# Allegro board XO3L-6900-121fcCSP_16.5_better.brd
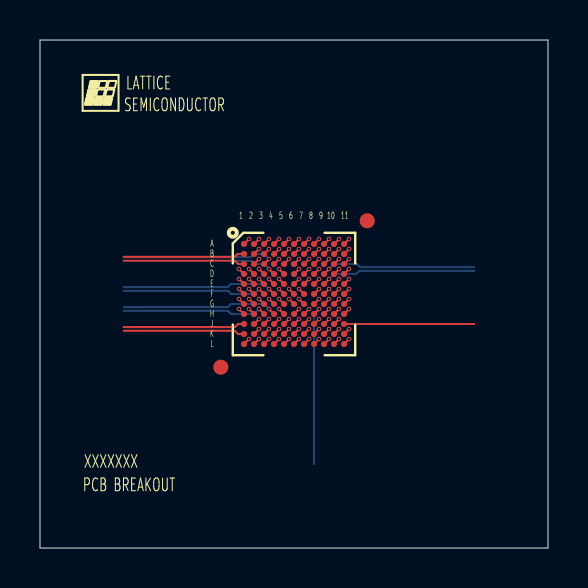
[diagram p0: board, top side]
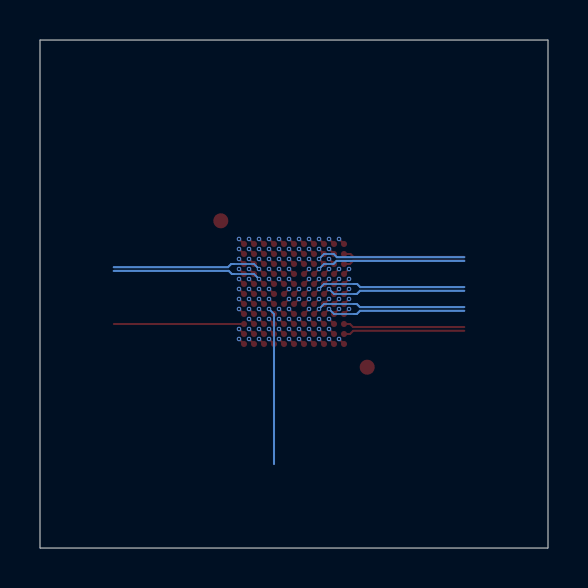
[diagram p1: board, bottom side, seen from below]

Outline 25.4 x 25.4 mm; copper layers: TOP, L2_GND, L3_SIGNAL1, L4_SIGNAL2, L5_PWR, BOTTOM. Coordinates in mm from the lower left corner of the outline.
Outline path: 0,25.4 25.4,25.4 25.4,0 0,0 0,25.4

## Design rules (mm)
net group CDPL10: nets PL10C PL10D
net group CDPT13: nets PT13C PT13D
net group CDPT15: nets PT15C PT15D
net group CDPT20: nets PT20C PT20D
net group CDPT23: nets PT23C PT23D
net group CDPT28: nets PT28C PT28D
net group PB3: nets PB3A PB3B
net group PB4: nets PB4A PB4B
net group PB7: nets PB7A PB7B
net group PB9: nets PB9A PB9B
net group PB10: nets PB10A PB10B
net group PB13: nets PB13A PB13B
net group PB20: nets PB20A PB20B
net group PB21: nets PB21A PB21B
net group PB24: nets PB24A PB24B
net group PB27: nets PB27A PB27B
net group PB29: nets PB29A PB29B
net group PB30: nets PB30A PB30B
net group PL3: nets PL3A PL3B
net group PL4: nets PL4A PL4B
net group PL6: nets PL6A PL6B
net group PL7: nets PL7A PL7B
net group PL8: nets PL8A PL8B
net group PL9: nets PL9A PL9B
net group PL14: nets PL14A PL14B
net group PL16: nets PL16A PL16B
net group PL17: nets PL17A PL17B
net group PL20: nets PL20A PL20B
net group PR2: nets PR2A PR2B
net group PR3: nets PR3A PR3B
net group PR5: nets PR5A PR5B
net group PR6: nets PR6A PR6B
net group PR8: nets PR8A PR8B
net group PR9: nets PR9A PR9B
net group PR10: nets PR10A PR10B
net group PR13: nets PR13A PR13B
net group PR14: nets PR14A PR14B
net group PR15: nets PR15A PR15B
net group PR16: nets PR16A PR16B
net group PR18: nets PR18A PR18B
net group PR19: nets PR19A PR19B
net group PT9: nets PT9A PT9B
net group PT11: nets PT11A PT11B
net group PT14: nets PT14A PT14B
net group PT18: nets PT18A PT18B
net group PT21: nets PT21A PT21B
net group PT24: nets PT24A PT24B
net group PT27: nets PT27A PT27B

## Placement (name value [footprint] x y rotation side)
BGA  -  [BGA121N50P11X11_600X600X100B-1]  12.7 12.7 270 top
NOREF  -  []  1.85 21.54 0 top

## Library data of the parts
BGA = BGA121N50P11X11_600X600X100B-1

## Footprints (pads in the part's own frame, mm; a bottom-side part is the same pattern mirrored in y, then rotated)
BGA121N50P11X11_600X600X100B-1
  round 0.75 smd: (-3.66,3.66) (3.66,-3.66)
  round 0.305 smd: A1(-2.5,-2.5) A2(-2.5,-2) A3(-2.5,-1.5) A4(-2.5,-1) A5(-2.5,-0.5) A6(-2.5,0) A7(-2.5,0.5) A8(-2.5,1) A9(-2.5,1.5) A10(-2.5,2) A11(-2.5,2.5) B1(-2,-2.5) B2(-2,-2) B3(-2,-1.5) B4(-2,-1) B5(-2,-0.5) B6(-2,0) B7(-2,0.5) B8(-2,1) B9(-2,1.5) B10(-2,2) B11(-2,2.5) C1(-1.5,-2.5) C2(-1.5,-2) C3(-1.5,-1.5) C4(-1.5,-1) C5(-1.5,-0.5) C6(-1.5,0) C7(-1.5,0.5) C8(-1.5,1) C9(-1.5,1.5) C10(-1.5,2) C11(-1.5,2.5) D1(-1,-2.5) D2(-1,-2) D3(-1,-1.5) D4(-1,-1) D5(-1,-0.5) D6(-1,0) D7(-1,0.5) D8(-1,1) D9(-1,1.5) D10(-1,2) D11(-1,2.5) E1(-0.5,-2.5) E2(-0.5,-2) E3(-0.5,-1.5) E4(-0.5,-1) E5(-0.5,-0.5) E6(-0.5,0) E7(-0.5,0.5) E8(-0.5,1) E9(-0.5,1.5) E10(-0.5,2) E11(-0.5,2.5) F1(0,-2.5) F2(0,-2) F3(0,-1.5) F4(0,-1) F5(0,-0.5) F6(0,0) F7(0,0.5) F8(0,1) F9(0,1.5) F10(0,2) F11(0,2.5) G1(0.5,-2.5) G2(0.5,-2) G3(0.5,-1.5) G4(0.5,-1) G5(0.5,-0.5) G6(0.5,0) G7(0.5,0.5) G8(0.5,1) G9(0.5,1.5) G10(0.5,2) G11(0.5,2.5) H1(1,-2.5) H2(1,-2) H3(1,-1.5) H4(1,-1) H5(1,-0.5) H6(1,0) H7(1,0.5) H8(1,1) H9(1,1.5) H10(1,2) H11(1,2.5) J1(1.5,-2.5) J2(1.5,-2) J3(1.5,-1.5) J4(1.5,-1) J5(1.5,-0.5) J6(1.5,0) J7(1.5,0.5) J8(1.5,1) J9(1.5,1.5) J10(1.5,2) J11(1.5,2.5) K1(2,-2.5) K2(2,-2) K3(2,-1.5) K4(2,-1) K5(2,-0.5) K6(2,0) K7(2,0.5) K8(2,1) K9(2,1.5) K10(2,2) K11(2,2.5) L1(2.5,-2.5) L2(2.5,-2) L3(2.5,-1.5) L4(2.5,-1) L5(2.5,-0.5) L6(2.5,0) L7(2.5,0.5) L8(2.5,1) L9(2.5,1.5) L10(2.5,2) L11(2.5,2.5)

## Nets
GND: BGA.A1 BGA.A11 BGA.E6 BGA.E7 BGA.F5 BGA.F6 BGA.G5 BGA.G6 BGA.L1 BGA.L11
VCC: BGA.D5 BGA.E5 BGA.F7 BGA.G7
VCCIO0: BGA.D6
VCCIO1: BGA.H5
VCCIO2: BGA.H6
VCCIO3: BGA.H8
VCCIO4: BGA.F8
VCCIO5: BGA.D8
PB3A: BGA.H9
PB3B: BGA.J9
PB4A: BGA.K10
PB4B: BGA.L10
PB7A: BGA.K9
PB7B: BGA.L9
PB9A: BGA.J8
PB9B: BGA.H7
PB10A: BGA.K8
PB10B: BGA.L8
PB13A: BGA.L7
PB13B: BGA.K7
PB15B: BGA.J7
PB20A: BGA.L6
PB20B: BGA.K6
PB21A: BGA.L5
PB21B: BGA.K5
PB23A: BGA.J6
PB24A: BGA.L4
PB24B: BGA.K4
PB27A: BGA.J5
PB27B: BGA.J4
PB29A: BGA.L3
PB29B: BGA.K3
PB30A: BGA.L2
PB30B: BGA.K2
PL3A: BGA.C9
PL3B: BGA.E8
PL4A: BGA.B10
PL4B: BGA.B11
PL6A: BGA.C10
PL6B: BGA.C11
PL7A: BGA.D9
PL7B: BGA.E9
PL8A: BGA.D10
PL8B: BGA.D11
PL9A: BGA.E10
PL9B: BGA.E11
PL10C: BGA.F11
PL10D: BGA.F10
PL13A: BGA.F9
PL14A: BGA.G11
PL14B: BGA.G10
PL16A: BGA.G9
PL16B: BGA.G8
PL17A: BGA.H11
PL17B: BGA.H10
PL19A: BGA.J11
PL20A: BGA.K11
PL20B: BGA.J10
PR2A: BGA.C2
PR2B: BGA.D3
PR3A: BGA.B1
PR3B: BGA.C1
PR5A: BGA.D2
PR5B: BGA.D1
PR6A: BGA.E4
PR6B: BGA.E3
PR8A: BGA.E2
PR8B: BGA.E1
PR9A: BGA.F3
PR9B: BGA.F4
PR10A: BGA.F2
PR10B: BGA.F1
PR13A: BGA.G1
PR13B: BGA.G2
PR14A: BGA.G3
PR14B: BGA.G4
PR15A: BGA.H1
PR15B: BGA.H2
PR16A: BGA.H3
PR16B: BGA.H4
PR18A: BGA.J1
PR18B: BGA.K1
PR19A: BGA.J2
PR19B: BGA.J3
PT9A: BGA.A10
PT9B: BGA.B9
PT10A: BGA.C8
PT11A: BGA.A9
PT11B: BGA.B8
PT13C: BGA.D7
PT13D: BGA.A8
PT14A: BGA.A7
PT14B: BGA.B7
PT15C: BGA.C7
PT15D: BGA.C6
PT18A: BGA.B6
PT18B: BGA.A6
PT20C: BGA.A5
PT20D: BGA.B5
PT21A: BGA.A4
PT21B: BGA.B4
PT23C: BGA.C5
PT23D: BGA.C4
PT24A: BGA.A3
PT24B: BGA.B3
PT27A: BGA.A2
PT27B: BGA.B2
PT28C: BGA.C3
PT28D: BGA.D4

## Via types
v1: diameter 0.224, hole 0.127, TOP to BOTTOM, 116 vias

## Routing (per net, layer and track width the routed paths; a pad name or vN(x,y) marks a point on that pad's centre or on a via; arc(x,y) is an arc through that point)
GND: length 3.5
  TOP w0.102: BGA.E7 v1(13.45,13.45) ; BGA.A1 v1(10.45,15.45) ; BGA.E6 v1(12.95,13.45) ; BGA.L11 v1(15.45,10.45) ; BGA.A11 v1(15.45,15.45) ; BGA.F6 v1(12.45,12.95) ; BGA.F5 v1(11.95,12.95) ; BGA.G5 v1(11.95,12.45) ; BGA.L1 v1(10.45,10.45) ; BGA.G6 v1(12.45,12.45)
VCC: length 1.4
  TOP w0.102: BGA.D5 v1(11.95,13.95) ; BGA.G7 v1(12.95,12.45) ; BGA.E5 v1(11.95,13.45) ; BGA.F7 v1(12.95,12.95)
VCCIO0: length 0.4
  TOP w0.102: BGA.D6 v1(12.95,13.95)
VCCIO1: length 0.4
  TOP w0.102: BGA.H5 v1(11.95,11.95)
VCCIO2: length 0.4
  TOP w0.102: BGA.H6 v1(12.95,11.95)
VCCIO3: length 8.2
  TOP w0.102: BGA.H8 v1(13.95,11.95)
  BOTTOM w0.089: v1(13.95,11.95) BGA.H8 13.7,10.22
  BOTTOM w0.102: 13.7,4.2 13.7,10.22
VCCIO4: length 0.4
  TOP w0.102: BGA.F8 v1(13.95,12.95)
VCCIO5: length 0.4
  TOP w0.102: BGA.D8 v1(13.95,13.95)
PB3A: length 7.8
  TOP w0.102: BGA.H9 v1(14.45,11.95)
  L4_SIGNAL2 w0.089: 15.21,11.7 14.7,11.7 v1(14.45,11.95)
  L4_SIGNAL2 w0.102: 15.21,11.7 15.37,11.54 21.71,11.54
PB3B: length 7.8
  TOP w0.102: BGA.J9 v1(14.45,11.45)
  L4_SIGNAL2 w0.089: 15.21,11.2 14.7,11.2 v1(14.45,11.45)
  L4_SIGNAL2 w0.102: 15.21,11.2 15.36,11.35 21.71,11.35
PB4A: length 7.2
  TOP w0.102: BGA.K10 v1(14.95,10.95)
  L3_SIGNAL1 w0.089: 14.7,10.22 BGA.K10 v1(14.95,10.95)
  L3_SIGNAL1 w0.102: 14.7,4.19 14.7,10.22
PB4B: length 6.6
  TOP w0.102: BGA.L10 v1(14.95,10.45)
  L3_SIGNAL1 w0.102: v1(14.95,10.45) 14.95,10.16 14.89,10.09 14.89,4.19
PB7A: length 7.2
  TOP w0.102: BGA.K9 v1(14.45,10.95)
  L3_SIGNAL1 w0.089: v1(14.45,10.95) BGA.K9 14.2,10.22
  L3_SIGNAL1 w0.102: 14.2,4.19 14.2,10.22
PB7B: length 6.6
  TOP w0.102: BGA.L9 v1(14.45,10.45)
  L3_SIGNAL1 w0.102: 14.39,4.19 14.39,10.09 14.45,10.16 v1(14.45,10.45)
PB9A: length 7.8
  TOP w0.102: BGA.J8 v1(13.95,11.45)
  L4_SIGNAL2 w0.089: 14.2,10.21 14.2,11.2 v1(13.95,11.45)
  L4_SIGNAL2 w0.102: 14.2,10.21 14.2,10.06 14.06,9.92 14.06,4.19
PB9B: length 8.3
  TOP w0.102: BGA.H7 v1(13.45,11.95)
  L4_SIGNAL2 w0.089: 13.7,10.26 13.7,11.7 v1(13.45,11.95)
  L4_SIGNAL2 w0.102: 13.7,10.26 13.7,10.08 13.87,9.91 13.87,4.19
PB10A: length 7.2
  TOP w0.102: BGA.K8 v1(13.95,10.95)
  L3_SIGNAL1 w0.089: v1(13.95,10.95) BGA.K8 13.7,10.22
  L3_SIGNAL1 w0.102: 13.7,4.19 13.7,10.22
PB10B: length 6.6
  TOP w0.102: BGA.L8 v1(13.95,10.45)
  L3_SIGNAL1 w0.102: v1(13.95,10.45) 13.95,10.16 13.89,10.09 13.89,4.19
PB13A: length 6.6
  TOP w0.102: BGA.L7 v1(13.45,10.45)
  L3_SIGNAL1 w0.102: 13.39,4.19 13.39,10.09 13.45,10.16 v1(13.45,10.45)
PB13B: length 7.2
  TOP w0.102: BGA.K7 v1(13.45,10.95)
  L3_SIGNAL1 w0.089: 13.2,10.22 BGA.K7 v1(13.45,10.95)
  L3_SIGNAL1 w0.102: 13.2,4.19 13.2,10.22
PB15B: length 7.7
  TOP w0.102: BGA.J7 v1(13.45,11.45)
  L4_SIGNAL2 w0.089: 13.2,10.23 BGA.J7 v1(13.45,11.45)
  L4_SIGNAL2 w0.102: 13.2,4.19 13.2,10.23
PB20A: length 6.6
  TOP w0.102: BGA.L6 v1(12.95,10.45)
  L3_SIGNAL1 w0.102: 12.89,4.19 12.89,10.09 12.95,10.16 v1(12.95,10.45)
PB20B: length 7.2
  TOP w0.102: BGA.K6 v1(12.95,10.95)
  L3_SIGNAL1 w0.089: v1(12.95,10.95) BGA.K6 12.7,10.22
  L3_SIGNAL1 w0.102: 12.7,4.19 12.7,10.22
PB21A: length 6.6
  TOP w0.102: BGA.L5 v1(12.45,10.45)
  L3_SIGNAL1 w0.102: 12.39,4.19 12.39,10.09 12.45,10.16 v1(12.45,10.45)
PB21B: length 7.2
  TOP w0.102: BGA.K5 v1(12.45,10.95)
  L3_SIGNAL1 w0.089: 12.2,10.22 BGA.K5 v1(12.45,10.95)
  L3_SIGNAL1 w0.102: 12.2,4.19 12.2,10.22
PB23A: length 7.7
  TOP w0.102: BGA.J6 v1(12.95,11.45)
  L4_SIGNAL2 w0.089: 12.7,10.23 BGA.J6 v1(12.95,11.45)
  L4_SIGNAL2 w0.102: 12.7,4.19 12.7,10.23
PB24A: length 6.6
  TOP w0.102: BGA.L4 v1(11.95,10.45)
  L3_SIGNAL1 w0.102: 11.89,4.19 11.89,10.09 11.95,10.16 v1(11.95,10.45)
PB24B: length 7.2
  TOP w0.102: BGA.K4 v1(11.95,10.95)
  L3_SIGNAL1 w0.089: 11.7,10.22 BGA.K4 v1(11.95,10.95)
  L3_SIGNAL1 w0.102: 11.7,4.19 11.7,10.22
PB27A: length 7.8
  TOP w0.102: BGA.J5 v1(12.45,11.45)
  L4_SIGNAL2 w0.089: 12.2,10.23 12.2,11.05 12.45,11.3 v1(12.45,11.45)
  L4_SIGNAL2 w0.102: 12.2,10.23 12.2,10.08 12.03,9.91 12.03,4.19
PB27B: length 7.8
  TOP w0.102: BGA.J4 v1(11.95,11.45)
  L4_SIGNAL2 w0.089: v1(11.95,11.45) BGA.J4 11.7,10.21
  L4_SIGNAL2 w0.102: 11.84,4.19 11.84,9.92 11.7,10.06 11.7,10.21
PB29A: length 6.6
  TOP w0.102: BGA.L3 v1(11.45,10.45)
  L3_SIGNAL1 w0.102: 11.39,4.19 11.39,10.09 11.45,10.16 v1(11.45,10.45)
PB29B: length 7.2
  TOP w0.102: BGA.K3 v1(11.45,10.95)
  L3_SIGNAL1 w0.089: v1(11.45,10.95) BGA.K3 11.2,10.22
  L3_SIGNAL1 w0.102: 11.2,4.19 11.2,10.22
PB30A: length 6.6
  TOP w0.102: BGA.L2 v1(10.95,10.45)
  L3_SIGNAL1 w0.102: v1(10.95,10.45) 10.95,10.16 10.89,10.09 10.89,4.19
PB30B: length 7.2
  TOP w0.102: BGA.K2 v1(10.95,10.95)
  L3_SIGNAL1 w0.089: v1(10.95,10.95) BGA.K2 10.7,10.22
  L3_SIGNAL1 w0.102: 10.7,4.19 10.7,10.22
PL3A: length 7.8
  TOP w0.102: BGA.C9 v1(14.45,14.45)
  L4_SIGNAL2 w0.089: 14.7,15.67 14.7,14.7 v1(14.45,14.45)
  L4_SIGNAL2 w0.102: 14.55,21.71 14.55,15.97 14.7,15.82 14.7,15.67
PL3B: length 8.8
  TOP w0.102: BGA.E8 v1(13.95,13.45)
  L4_SIGNAL2 w0.089: 14.2,15.66 14.2,13.7 v1(13.95,13.45)
  L4_SIGNAL2 w0.102: 14.36,21.71 14.36,15.96 14.2,15.8 14.2,15.66
PL4A: length 7.2
  TOP w0.102: BGA.B10 v1(14.95,14.95)
  L3_SIGNAL1 w0.089: v1(14.95,14.95) 15.2,15.2 15.68,15.2
  L3_SIGNAL1 w0.102: 21.71,15.2 15.68,15.2
PL4B: length 6.6
  TOP w0.102: BGA.B11 v1(15.45,14.95)
  L3_SIGNAL1 w0.102: v1(15.45,14.95) 15.74,14.95 15.8,15.01 21.71,15.01
PL6A: length 7.2
  TOP w0.102: BGA.C10 v1(14.95,14.45)
  L3_SIGNAL1 w0.089: v1(14.95,14.45) 15.2,14.7 15.68,14.7
  L3_SIGNAL1 w0.102: 21.71,14.7 15.68,14.7
PL6B: length 6.6
  TOP w0.102: BGA.C11 v1(15.45,14.45)
  L3_SIGNAL1 w0.102: v1(15.45,14.45) 15.74,14.45 15.8,14.51 21.71,14.51
PL7A: length 7.8
  TOP w0.102: BGA.D9 v1(14.45,13.95)
  BOTTOM w0.089: v1(14.45,13.95) 14.7,14.2 15.69,14.2
  BOTTOM w0.102: 21.71,14.04 16,14.04 15.84,14.2 15.69,14.2
PL7B: length 7.8
  TOP w0.102: BGA.E9 v1(14.45,13.45)
  BOTTOM w0.089: v1(14.45,13.45) 14.7,13.7 15.69,13.7
  BOTTOM w0.102: 21.71,13.85 15.96,13.85 15.81,13.7 15.69,13.7
PL8A: length 7.2
  TOP w0.102: BGA.D10 v1(14.95,13.95)
  L3_SIGNAL1 w0.089: v1(14.95,13.95) 15.2,14.2 15.68,14.2
  L3_SIGNAL1 w0.102: 21.71,14.2 15.68,14.2
PL8B: length 6.6
  TOP w0.102: BGA.D11 v1(15.45,13.95)
  L3_SIGNAL1 w0.102: v1(15.45,13.95) 15.74,13.95 15.8,14.01 21.71,14.01
PL9A: length 7.2
  TOP w0.102: BGA.E10 v1(14.95,13.45)
  L3_SIGNAL1 w0.089: 15.68,13.7 15.2,13.7 v1(14.95,13.45)
  L3_SIGNAL1 w0.102: 21.71,13.7 15.68,13.7
PL9B: length 6.6
  TOP w0.102: BGA.E11 v1(15.45,13.45)
  L3_SIGNAL1 w0.102: v1(15.45,13.45) 15.74,13.45 15.8,13.51 21.71,13.51
PL10C: length 6.6
  TOP w0.102: BGA.F11 v1(15.45,12.95)
  L3_SIGNAL1 w0.102: 21.71,13.01 15.8,13.01 15.74,12.95 v1(15.45,12.95)
PL10D: length 7.2
  TOP w0.102: BGA.F10 v1(14.95,12.95)
  L3_SIGNAL1 w0.089: v1(14.95,12.95) 15.2,13.2 15.68,13.2
  L3_SIGNAL1 w0.102: 21.71,13.2 15.68,13.2
PL13A: length 7.7
  TOP w0.102: BGA.F9 v1(14.45,12.95)
  L4_SIGNAL2 w0.089: v1(14.45,12.95) 14.7,13.2 15.69,13.2
  L4_SIGNAL2 w0.102: 21.71,13.2 15.69,13.2
PL14A: length 6.6
  TOP w0.102: BGA.G11 v1(15.45,12.45)
  L3_SIGNAL1 w0.102: 21.71,12.51 15.8,12.51 15.74,12.45 v1(15.45,12.45)
PL14B: length 7.2
  TOP w0.102: BGA.G10 v1(14.95,12.45)
  L3_SIGNAL1 w0.089: v1(14.95,12.45) 15.2,12.7 15.68,12.7
  L3_SIGNAL1 w0.102: 21.71,12.7 15.68,12.7
PL16A: length 7.8
  TOP w0.102: BGA.G9 v1(14.45,12.45)
  L4_SIGNAL2 w0.089: 15.69,12.2 14.7,12.2 v1(14.45,12.45)
  L4_SIGNAL2 w0.102: 15.69,12.2 15.78,12.2 15.94,12.36 21.71,12.36
PL16B: length 8.3
  TOP w0.102: BGA.G8 v1(13.95,12.45)
  L4_SIGNAL2 w0.089: 15.67,12.7 14.2,12.7 v1(13.95,12.45)
  L4_SIGNAL2 w0.102: 21.71,12.54 15.95,12.54 15.79,12.7 15.67,12.7
PL17A: length 6.6
  TOP w0.102: BGA.H11 v1(15.45,11.95)
  L3_SIGNAL1 w0.102: v1(15.45,11.95) 15.74,11.95 15.8,12.01 21.71,12.01
PL17B: length 7.2
  TOP w0.102: BGA.H10 v1(14.95,11.95)
  L3_SIGNAL1 w0.089: 15.68,12.2 15.2,12.2 v1(14.95,11.95)
  L3_SIGNAL1 w0.102: 21.71,12.2 15.68,12.2
PL19A: length 6.5
  TOP w0.102: 21.7,11.2 BGA.J11
PL20A: length 7.1
  TOP w0.102: BGA.K11 v1(15.45,10.95)
  L3_SIGNAL1 w0.102: v1(15.45,10.95) 15.34,11.06 15.34,11.21 15.58,11.44 21.71,11.44
PL20B: length 7.3
  TOP w0.102: BGA.J10 v1(14.95,11.45)
  L3_SIGNAL1 w0.102: v1(14.95,11.45) 15.06,11.34 15.21,11.34 15.5,11.63 21.71,11.63
PR2A: length 7.1
  TOP w0.102: BGA.C2 v1(10.95,14.45)
  L4_SIGNAL2 w0.102: 4.19,14.45 v1(10.95,14.45)
PR2B: length 7.2
  TOP w0.102: BGA.D3 v1(10.95,13.95)
  L4_SIGNAL2 w0.102: v1(10.95,13.95) 10.64,14.26 4.19,14.26
PR3A: length 6.1
  TOP w0.102: BGA.B1 9.87,14.7 9.73,14.55 4.19,14.55
PR3B: length 6.1
  TOP w0.102: BGA.C1 9.9,14.2 9.74,14.37 4.19,14.37
PR5A: length 7.2
  TOP w0.102: BGA.D2 v1(10.45,13.95)
  L3_SIGNAL1 w0.102: v1(10.45,13.95) 10.29,14.11 10.29,14.47 9.98,14.78 4.19,14.78
PR5B: length 6.9
  TOP w0.102: BGA.D1 v1(9.95,13.95)
  L3_SIGNAL1 w0.102: v1(9.95,13.95) 10.11,14.11 10.11,14.39 9.91,14.59 4.19,14.59
PR6A: length 7.8
  TOP w0.102: BGA.E4 v1(11.45,13.45)
  L4_SIGNAL2 w0.089: 9.76,13.2 11.2,13.2 v1(11.45,13.45)
  L4_SIGNAL2 w0.102: 9.76,13.2 9.58,13.2 9.41,13.37 4.19,13.37
PR6B: length 7.3
  TOP w0.102: BGA.E3 v1(10.95,13.45)
  L4_SIGNAL2 w0.089: v1(10.95,13.45) 10.7,13.7 9.71,13.7
  L4_SIGNAL2 w0.102: 9.71,13.7 9.56,13.7 9.42,13.56 4.19,13.56
PR8A: length 6.7
  TOP w0.102: BGA.E2 v1(10.45,13.45)
  L3_SIGNAL1 w0.089: 9.72,13.7 10.2,13.7 v1(10.45,13.45)
  L3_SIGNAL1 w0.102: 4.19,13.7 9.72,13.7
PR8B: length 6.1
  TOP w0.102: BGA.E1 v1(9.95,13.45)
  L3_SIGNAL1 w0.102: v1(9.95,13.45) 9.66,13.45 9.6,13.51 4.19,13.51
PR9A: length 7.3
  TOP w0.102: BGA.F3 v1(10.95,12.95)
  BOTTOM w0.089: 9.71,12.7 10.7,12.7 v1(10.95,12.95)
  BOTTOM w0.102: 4.19,12.86 9.4,12.86 9.56,12.7 9.71,12.7
PR9B: length 7.8
  TOP w0.102: BGA.F4 v1(11.45,12.95)
  BOTTOM w0.089: 9.72,13.2 11.2,13.2 v1(11.45,12.95)
  BOTTOM w0.102: 9.72,13.2 9.54,13.2 9.39,13.05 4.19,13.05
PR10A: length 6.7
  TOP w0.102: BGA.F2 v1(10.45,12.95)
  L3_SIGNAL1 w0.089: 9.72,13.2 10.2,13.2 v1(10.45,12.95)
  L3_SIGNAL1 w0.102: 4.19,13.2 9.72,13.2
PR10B: length 6.1
  TOP w0.102: BGA.F1 v1(9.95,12.95)
  L3_SIGNAL1 w0.102: 4.19,13.01 9.6,13.01 9.66,12.95 v1(9.95,12.95)
PR13A: length 6.1
  TOP w0.102: BGA.G1 v1(9.95,12.45)
  L3_SIGNAL1 w0.102: 4.19,12.51 9.6,12.51 9.66,12.45 v1(9.95,12.45)
PR13B: length 6.7
  TOP w0.102: BGA.G2 v1(10.45,12.45)
  L3_SIGNAL1 w0.089: v1(10.45,12.45) 10.2,12.7 9.72,12.7
  L3_SIGNAL1 w0.102: 4.19,12.7 9.72,12.7
PR14A: length 7.3
  TOP w0.102: BGA.G3 v1(10.95,12.45)
  L4_SIGNAL2 w0.089: v1(10.95,12.45) 10.7,12.7 9.71,12.7
  L4_SIGNAL2 w0.102: 9.71,12.7 9.56,12.7 9.42,12.56 4.19,12.56
PR14B: length 7.8
  TOP w0.102: BGA.G4 v1(11.45,12.45)
  L4_SIGNAL2 w0.089: 9.76,12.2 11.2,12.2 v1(11.45,12.45)
  L4_SIGNAL2 w0.102: 4.19,12.37 9.41,12.37 9.58,12.2 9.76,12.2
PR15A: length 6.7
  TOP w0.102: BGA.H1 v1(9.95,11.95)
  L3_SIGNAL1 w0.102: v1(9.95,11.95) 10.11,11.79 10.11,11.57 10.02,11.48 4.2,11.48
PR15B: length 7.1
  TOP w0.102: BGA.H2 v1(10.45,11.95)
  L3_SIGNAL1 w0.102: v1(10.45,11.95) 10.29,11.79 10.29,11.49 10.1,11.29 4.2,11.29
PR16A: length 7.3
  TOP w0.102: BGA.H3 v1(10.95,11.95)
  BOTTOM w0.089: 9.71,11.7 10.7,11.7 v1(10.95,11.95)
  BOTTOM w0.102: 4.19,11.86 9.4,11.86 9.56,11.7 9.71,11.7
PR16B: length 7.8
  TOP w0.102: BGA.H4 v1(11.45,11.95)
  BOTTOM w0.089: 9.72,12.2 11.2,12.2 v1(11.45,11.95)
  BOTTOM w0.102: 9.72,12.2 9.56,12.2 9.41,12.05 4.19,12.05
PR18A: length 6.1
  TOP w0.102: 4.19,11.05 9.75,11.05 9.9,11.2 BGA.J1
PR18B: length 6.1
  TOP w0.102: 4.19,10.86 9.74,10.86 9.9,10.7 BGA.K1
PR19A: length 7.1
  TOP w0.102: BGA.J2 v1(10.95,11.45)
  L4_SIGNAL2 w0.102: 4.19,11.39 10.57,11.39 10.63,11.45 v1(10.95,11.45)
PR19B: length 7.7
  TOP w0.102: BGA.J3 v1(11.45,11.45)
  L4_SIGNAL2 w0.089: 10.61,11.2 BGA.J3 v1(11.45,11.45)
  L4_SIGNAL2 w0.102: 4.19,11.2 10.61,11.2
PT9A: length 6.6
  TOP w0.102: BGA.A10 v1(14.95,15.45)
  L3_SIGNAL1 w0.102: 14.89,21.71 14.89,15.8 14.95,15.74 v1(14.95,15.45)
PT9B: length 7.2
  TOP w0.102: BGA.B9 v1(14.45,14.95)
  L3_SIGNAL1 w0.089: v1(14.45,14.95) 14.7,15.2 14.7,15.68
  L3_SIGNAL1 w0.102: 14.7,15.68 14.7,21.71
PT10A: length 7.7
  TOP w0.102: BGA.C8 v1(13.95,14.45)
  L4_SIGNAL2 w0.089: v1(13.95,14.45) 13.7,14.7 13.7,15.68
  L4_SIGNAL2 w0.102: 13.7,15.68 13.7,21.73
PT11A: length 6.6
  TOP w0.102: BGA.A9 v1(14.45,15.45)
  L3_SIGNAL1 w0.102: 14.39,21.71 14.39,15.81 14.45,15.74 v1(14.45,15.45)
PT11B: length 7.2
  TOP w0.102: BGA.B8 v1(13.95,14.95)
  L3_SIGNAL1 w0.089: v1(13.95,14.95) 14.2,15.2 14.2,15.68
  L3_SIGNAL1 w0.102: 14.2,15.68 14.2,21.71
PT13C: length 8.2
  TOP w0.102: BGA.D7 v1(13.45,13.95)
  L3_SIGNAL1 w0.089: v1(13.45,13.95) 13.7,14.2 13.7,15.74
  L3_SIGNAL1 w0.102: 13.7,15.74 13.7,21.71
PT13D: length 6.6
  TOP w0.102: BGA.A8 v1(13.95,15.45)
  L3_SIGNAL1 w0.102: 13.89,21.71 13.89,15.8 13.95,15.74 v1(13.95,15.45)
PT14A: length 6.6
  TOP w0.102: BGA.A7 v1(13.45,15.45)
  L3_SIGNAL1 w0.102: v1(13.45,15.45) 13.45,15.74 13.39,15.8 13.39,21.71
PT14B: length 7.2
  TOP w0.102: BGA.B7 v1(13.45,14.95)
  L3_SIGNAL1 w0.089: v1(13.45,14.95) 13.2,15.2 13.2,15.68
  L3_SIGNAL1 w0.102: 13.2,21.71 13.2,15.68
PT15C: length 7.8
  TOP w0.102: BGA.C7 v1(13.45,14.45)
  L4_SIGNAL2 w0.089: 13.2,15.67 13.2,14.7 v1(13.45,14.45)
  L4_SIGNAL2 w0.102: 13.2,15.67 13.2,15.82 13.04,15.98 13.04,21.71
PT15D: length 7.8
  TOP w0.102: BGA.C6 v1(12.95,14.45)
  L4_SIGNAL2 w0.089: v1(12.95,14.45) 12.7,14.7 12.7,15.67
  L4_SIGNAL2 w0.102: 12.85,21.71 12.85,15.98 12.7,15.82 12.7,15.67
PT18A: length 7.2
  TOP w0.102: BGA.B6 v1(12.95,14.95)
  L3_SIGNAL1 w0.089: 12.7,15.68 12.7,15.2 v1(12.95,14.95)
  L3_SIGNAL1 w0.102: 12.7,21.71 12.7,15.68
PT18B: length 6.6
  TOP w0.102: BGA.A6 v1(12.95,15.45)
  L3_SIGNAL1 w0.102: v1(12.95,15.45) 12.95,15.74 12.89,15.8 12.89,21.71
PT20C: length 6.6
  TOP w0.102: BGA.A5 v1(12.45,15.45)
  L3_SIGNAL1 w0.102: v1(12.45,15.45) 12.45,15.74 12.39,15.8 12.39,21.71
PT20D: length 7.2
  TOP w0.102: BGA.B5 v1(12.45,14.95)
  L3_SIGNAL1 w0.089: 12.2,15.68 12.2,15.2 v1(12.45,14.95)
  L3_SIGNAL1 w0.102: 12.2,21.71 12.2,15.68
PT21A: length 6.6
  TOP w0.102: BGA.A4 v1(11.95,15.45)
  L3_SIGNAL1 w0.102: 11.89,21.71 11.89,15.8 11.95,15.74 v1(11.95,15.45)
PT21B: length 7.2
  TOP w0.102: BGA.B4 v1(11.95,14.95)
  L3_SIGNAL1 w0.089: 11.7,15.68 11.7,15.2 v1(11.95,14.95)
  L3_SIGNAL1 w0.102: 11.7,21.71 11.7,15.68
PT23C: length 7.8
  TOP w0.102: BGA.C5 v1(12.45,14.45)
  L4_SIGNAL2 w0.089: 12.2,15.67 12.2,14.7 v1(12.45,14.45)
  L4_SIGNAL2 w0.102: 12.05,21.71 12.05,15.98 12.2,15.82 12.2,15.67
PT23D: length 7.8
  TOP w0.102: BGA.C4 v1(11.95,14.45)
  L4_SIGNAL2 w0.089: 11.7,15.67 11.7,14.7 v1(11.95,14.45)
  L4_SIGNAL2 w0.102: 11.86,21.71 11.86,15.98 11.7,15.82 11.7,15.67
PT24A: length 6.6
  TOP w0.102: BGA.A3 v1(11.45,15.45)
  L3_SIGNAL1 w0.102: v1(11.45,15.45) 11.45,15.74 11.39,15.8 11.39,21.71
PT24B: length 7.2
  TOP w0.102: BGA.B3 v1(11.45,14.95)
  L3_SIGNAL1 w0.089: 11.2,15.68 11.2,15.2 v1(11.45,14.95)
  L3_SIGNAL1 w0.102: 11.2,21.71 11.2,15.68
PT27A: length 6.6
  TOP w0.102: BGA.A2 v1(10.95,15.45)
  L3_SIGNAL1 w0.102: v1(10.95,15.45) 10.95,15.74 10.89,15.8 10.89,21.71
PT27B: length 7.2
  TOP w0.102: BGA.B2 v1(10.95,14.95)
  L3_SIGNAL1 w0.089: v1(10.95,14.95) 10.7,15.2 10.7,15.68
  L3_SIGNAL1 w0.102: 10.7,21.71 10.7,15.68
PT28C: length 7.8
  TOP w0.102: BGA.C3 v1(11.45,14.45)
  BOTTOM w0.089: 10.72,14.7 11.2,14.7 v1(11.45,14.45)
  BOTTOM w0.102: 10.72,14.7 10.56,14.54 4.19,14.54
PT28D: length 7.8
  TOP w0.102: BGA.D4 v1(11.45,13.95)
  BOTTOM w0.089: v1(11.45,13.95) 11.2,14.2 10.73,14.2
  BOTTOM w0.102: 10.73,14.2 10.57,14.35 4.19,14.35

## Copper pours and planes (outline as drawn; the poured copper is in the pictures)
GND on L2_GND: 1.27,1.27 1.27,24.13 24.13,24.13 24.13,1.27
VCC on L5_PWR: 1.32,12.28 1.32,24.1 9.98,24.1 9.98,16.28 12.18,14.09 12.18,13.67 12.5,13.35 13.35,13.35 13.35,12.28
VCCIO0 on L5_PWR: 12.38,13.72 12.38,14.17 10.16,16.38 10.16,24.1 21.39,24.1 13.35,16.06 13.35,13.57 12.53,13.57
VCCIO1 on L5_PWR: 12.37,12.1 12.37,1.3 1.3,1.3 1.3,12.1
VCCIO2 on L5_PWR: 12.55,12.1 12.55,1.3 24.1,1.3 24.1,4.83 20.95,4.83 13.67,12.1
VCCIO4 on L5_PWR: 13.54,13.35 13.54,12.53 21.04,5.03 24.1,5.03 24.1,13.35
VCCIO5 on L5_PWR: 13.55,13.57 13.55,16.01 21.64,24.1 24.1,24.1 24.1,13.57

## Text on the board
User.Comments: R.P | REN | 09/05/14 | DWG NO: | XXXX-##XXXXX | REVISION | 1.0 | SHEET | 1 | OF | LATTICE SEMICONDUCTOR CORPORATION | DESCRIPTION
Ref Des/Silkscreen Top: A | B | C | D | E | F | G | H | J | K | L | 1 | 2 | 3 | 4 | 5 | 6 | 7 | 8 | 9 | 10 | 11 | PCB BREAKOUT | XXXXXXX | SEMICONDUCTOR | LATTICE
PAGE_OUTLINE: SPECIAL INSTRUCTIONS: | LIKE VIA FILL | SPECIFY ANY SPECIAL INSTRUCTIONS | GND     PLANE  (L2) | TOP SIDE       (L1) | SIGNAL2        (L4) | POWER   PLANE  (L5) | SIGNAL1        (L3) | BOTTOM SIDE    (L6) | BOTTOM SILKSCREEN | TOP SOLDERMASK | BOTTOM SOLDERMASK | TOP SILKSCREEN | DESIGNED BY: | APPROVED BY: | SIGNATURES         DATE | REV | 1 | INITIAL RELEASE | ESCAPE VIA DRILL | TRACE WIDTH/SPACE | ESCAPE VIA PAD | LAND OPENING | PACKAGE SIZE | LAND PAD | PITCH | DESCRIPTION | 0.102/0.086 | 0.2235 | 0.3048 | 0.127 | 6 x 6 | 0.50 | MM | MM/DD/YYYY | DATE | 236.2x236.2 | 4.00/3.40 | 19.69 | 8.80 | 12.00 | 5.00 | MILS | APPEOVED | X. XXXXX | 4 LAYER STACKUP | PCB BREAKOUT DETAILS | REVISION
PLACE_BOUND_TOP: FIGURE | SIZE | 5.0 | DRILL CHART: TOP to BOTTOM | ALL UNITS ARE IN MILS | PLATED | QTY | 116
